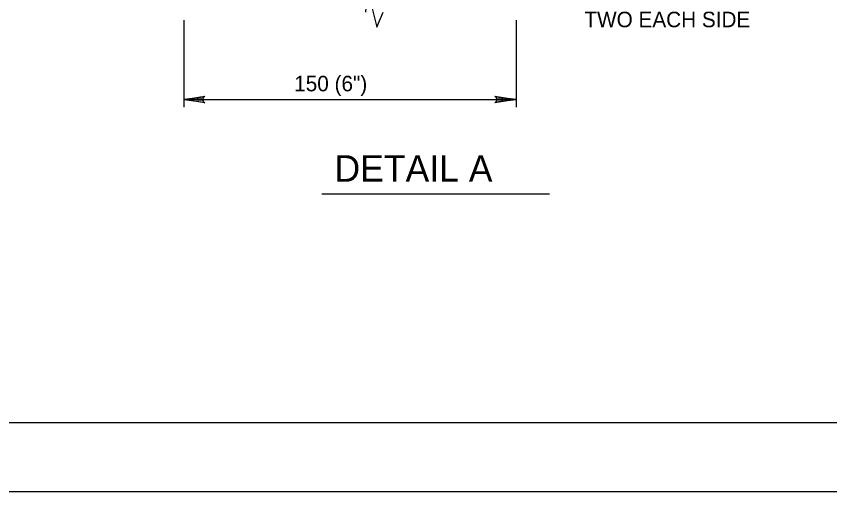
# Model space of a CAD drawing. Extents: x 638447 to 639352, y 298406 to 299000.
# Drawn here: x 638547.9 to 638724.2, y 298406.5 to 298509.5 of the extents above; entities that cross this region are included whole.
import ezdxf

# ---------------------------------------------------------------- set-up
doc = ezdxf.new("R2010")
doc.units = 0
for name, color, linetype in [('1', 7, 'Continuous'), ('2', 7, 'Continuous'), ('3', 7, 'Continuous'), ('PLT-BNDY', 7, 'Continuous')]:
    doc.layers.add(name, color=color, linetype=linetype)

msp = doc.modelspace()

# ---------------------------------------------------------------- linework, layer by layer
at = {"layer": '1'}
msp.add_lwpolyline([(639272.394625, 298421.4725), (639272.394625, 298985.4725), (638486.394625, 298985.4725), (638486.394625, 298421.4725), (639272.394625, 298421.4725), (639272.394625, 298447.8315), (639072.394625, 298447.8315), (639072.394625, 298512.509), (639272.394625, 298512.509), (639272.394625, 298541.4725), (639072.394625, 298541.4725), (639072.394625, 298421.4725), (639151.196125, 298421.4725), (639151.196125, 298447.8315), (639151.196125, 298421.4725), (639228.196125, 298421.4725), (639228.196125, 298447.8315), (639228.196125, 298435.515), (639272.394625, 298435.515)], dxfattribs=at)
at = {"layer": '2'}
for p, q in [((638584.202375, 298508.674), (638584.202375, 298489.77)), ((638656.202375, 298508.674), (638656.202375, 298489.77)), ((638584.202375, 298491.45), (638629.646375, 298491.45)), ((638629.646375, 298491.45), (638656.202375, 298491.45))]:
    msp.add_line(p, q, dxfattribs=at)
for points in [[(638623.640375, 298510.354), (638623.992375, 298515.278), (638626.070375, 298507.138), (638627.450375, 298510.354)], [(638588.560375, 298490.902), (638588.398375, 298491.218), (638584.202375, 298491.45), (638588.560375, 298490.902), (638588.784375, 298490.712), (638584.202375, 298491.45), (638588.394375, 298491.658), (638588.548375, 298491.97), (638584.202375, 298491.45), (638588.784375, 298492.178), (638588.548375, 298491.97)], [(638651.842375, 298491.998), (638652.004375, 298491.682), (638656.202375, 298491.45), (638651.842375, 298491.998), (638651.618375, 298492.188), (638656.202375, 298491.45), (638652.008375, 298491.242), (638651.854375, 298490.93), (638656.202375, 298491.45), (638651.618375, 298490.722), (638651.854375, 298490.93)]]:
    msp.add_lwpolyline(points, dxfattribs=at)
at = {"layer": '3'}
msp.add_line((638614.094375, 298471.01), (638663.442375, 298471.01), dxfattribs=at)
at = {"layer": 'PLT-BNDY'}
msp.add_lwpolyline([(638447.394625, 299000.4725), (639288.394625, 299000.4725), (639288.394625, 298406.4725), (638447.394625, 298406.4725)], close=True, dxfattribs=at)

# ---------------------------------------------------------------- texts
at = {"layer": '3'}
for s, height, p in [('TWO EACH SIDE', 3.359988, (638671.022375, 298507.120036)), ('150 (6")', 3.36, (638608.142625, 298493.2365)), ('DETAIL A', 5.76, (638616.870375, 298473.638))]:
    msp.add_text(s, height=height, dxfattribs=at).set_placement(p)

doc.saveas('drawing.dxf')
